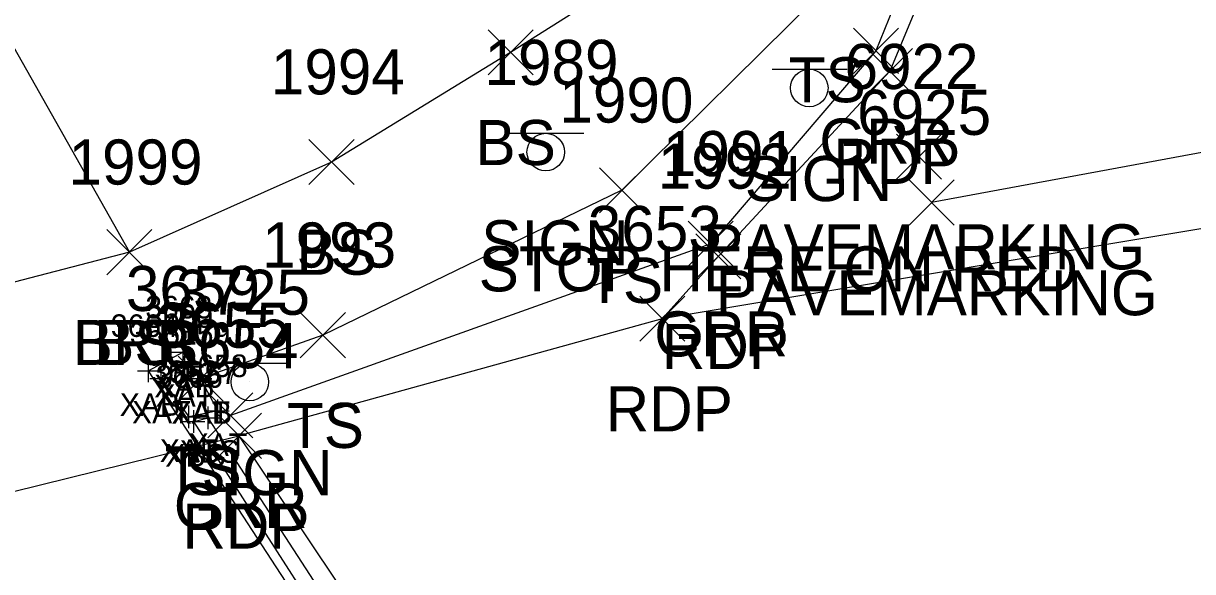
# Model space of a CAD drawing. Extents: x 1505656 to 1508446, y 700805 to 703031.
# Drawn here: x 1506524.5 to 1506576.4, y 701818 to 701842.3 of the extents above; entities that cross this region are included whole.
import ezdxf

# ---------------------------------------------------------------- set-up
doc = ezdxf.new("R2010")
doc.units = 0
for name, color, linetype in [('B_A', 7, 'Continuous'), ('B_I', 7, 'Continuous'), ('B_TIC', 7, 'Continuous'), ('BELB', 7, 'Continuous'), ('BSE', 7, 'Continuous'), ('BSUBM', 7, 'Continuous'), ('L_A', 7, 'Continuous'), ('L_I', 7, 'Continuous'), ('L_TIC', 7, 'Continuous'), ('LABL', 7, 'Continuous'), ('LELB', 7, 'Continuous'), ('P_A', 7, 'Continuous'), ('P_I', 7, 'Continuous'), ('P_TIC', 7, 'Continuous'), ('PET', 7, 'Continuous'), ('R_A', 7, 'Continuous'), ('R_I', 7, 'Continuous'), ('R_TIC', 7, 'Continuous'), ('RGR', 7, 'Continuous'), ('S_A', 7, 'Continuous'), ('S_C', 7, 'Continuous'), ('S_I', 7, 'Continuous'), ('S_TIC', 7, 'Continuous'), ('SSGN', 7, 'Continuous'), ('STS', 7, 'Continuous')]:
    doc.layers.add(name, color=color, linetype=linetype)

msp = doc.modelspace()

# ---------------------------------------------------------------- linework, layer by layer
at = {"layer": 'B_TIC'}
for p, q in [((1506531.566, 701827.682), (1506531.642, 701827.682)), ((1506531.638, 701827.266), (1506531.713, 701827.266)), ((1506530.036, 701826.863), (1506530.112, 701826.863)), ((1506530.036, 701826.863), (1506530.112, 701826.863)), ((1506530.593, 701826.524), (1506530.668, 701826.524)), ((1506532.341, 701826.513), (1506532.417, 701826.513)), ((1506532.341, 701826.513), (1506532.417, 701826.513)), ((1506531.827, 701824.82), (1506531.902, 701824.82)), ((1506531.827, 701824.82), (1506531.902, 701824.82)), ((1506532.035, 701824.61), (1506532.111, 701824.61)), ((1506532.675, 701824.779), (1506532.751, 701824.779)), ((1506532.675, 701824.779), (1506532.751, 701824.779)), ((1506533.107, 701825.083), (1506533.183, 701825.083)), ((1506533.107, 701825.083), (1506533.183, 701825.083))]:
    msp.add_line(p, q, dxfattribs=at)
for points in [[(1506531.563, 701827.182), (1506531.563, 701828.182)], [(1506531.634, 701826.766), (1506531.634, 701827.766)], [(1506530.033, 701826.363), (1506530.033, 701827.363)], [(1506530.033, 701826.363), (1506530.033, 701827.363)], [(1506531.063, 701827.682), (1506532.063, 701827.682)], [(1506531.134, 701827.266), (1506532.134, 701827.266)], [(1506529.533, 701826.863), (1506530.533, 701826.863)], [(1506529.533, 701826.863), (1506530.533, 701826.863)], [(1506530.589, 701826.024), (1506530.589, 701827.024)], [(1506532.338, 701826.013), (1506532.338, 701827.013)], [(1506532.338, 701826.013), (1506532.338, 701827.013)], [(1506530.089, 701826.524), (1506531.089, 701826.524)], [(1506531.838, 701826.513), (1506532.838, 701826.513)], [(1506531.838, 701826.513), (1506532.838, 701826.513)], [(1506531.823, 701824.32), (1506531.823, 701825.32)], [(1506531.823, 701824.32), (1506531.823, 701825.32)], [(1506532.032, 701824.11), (1506532.032, 701825.11)], [(1506532.672, 701824.279), (1506532.672, 701825.279)], [(1506532.672, 701824.279), (1506532.672, 701825.279)], [(1506533.104, 701824.583), (1506533.104, 701825.583)], [(1506533.104, 701824.583), (1506533.104, 701825.583)], [(1506531.323, 701824.82), (1506532.323, 701824.82)], [(1506531.323, 701824.82), (1506532.323, 701824.82)], [(1506531.532, 701824.61), (1506532.532, 701824.61)], [(1506532.172, 701824.779), (1506533.172, 701824.779)], [(1506532.172, 701824.779), (1506533.172, 701824.779)], [(1506532.604, 701825.083), (1506533.604, 701825.083)], [(1506532.604, 701825.083), (1506533.604, 701825.083)]]:
    msp.add_lwpolyline(points, dxfattribs=at)
at = {"layer": 'BELB'}
msp.add_lwpolyline([(1506511.318, 701818.378), (1506534.041, 701823.974)], dxfattribs=at)
at = {"layer": 'BSE'}
for points in [[(1506550.561, 701797.232), (1506549.7, 701797.111), (1506532.032, 701824.61), (1506532.672, 701824.779)], [(1506550.561, 701797.232), (1506532.672, 701824.779)]]:
    msp.add_lwpolyline(points, dxfattribs=at)
at = {"layer": 'BSUBM'}
for points in [[(1506532.338, 701826.513), (1506531.563, 701827.682), (1506530.033, 701826.863)], [(1506533.104, 701825.083), (1506532.338, 701826.513), (1506531.634, 701827.266), (1506530.589, 701826.524), (1506531.823, 701824.82)], [(1506552.506, 701796.25), (1506553.111, 701794.844), (1506551.655, 701793.729), (1506549.57, 701796.872), (1506530.033, 701826.863)], [(1506533.104, 701825.083), (1506531.823, 701824.82)]]:
    msp.add_lwpolyline(points, dxfattribs=at)
at = {"layer": 'L_TIC'}
for points in [[(1506545.101, 701839.985), (1506547.101, 701841.985)], [(1506547.101, 701839.985), (1506545.101, 701841.985)], [(1506537.15, 701835.12), (1506539.15, 701837.12)], [(1506539.15, 701835.12), (1506537.15, 701837.12)], [(1506550.045, 701833.869), (1506552.045, 701835.869)], [(1506552.045, 701833.869), (1506550.045, 701835.869)], [(1506528.177, 701831.12), (1506530.177, 701833.12)], [(1506530.177, 701831.12), (1506528.177, 701833.12)], [(1506528.177, 701831.12), (1506530.177, 701833.12)], [(1506530.177, 701831.12), (1506528.177, 701833.12)], [(1506536.765, 701827.439), (1506538.765, 701829.439)], [(1506538.765, 701827.439), (1506536.765, 701829.439)], [(1506531.338, 701825.513), (1506533.338, 701827.513)], [(1506533.338, 701825.513), (1506531.338, 701827.513)]]:
    msp.add_lwpolyline(points, dxfattribs=at)
at = {"layer": 'LABL'}
msp.add_lwpolyline([(1506097.891, 702451.479), (1506119.326, 702422.589), (1506147.143, 702381.233), (1506170.739, 702339.268), (1506181.047, 702317.334), (1506195.309, 702300.853), (1506204.63, 702289.221), (1506217.936, 702268.002), (1506249.758, 702230.45), (1506275.61, 702192.019), (1506301.13, 702151.48), (1506333.13, 702110.445), (1506362.684, 702074.768), (1506393.244, 702036.244), (1506419.011, 702002.404), (1506440.789, 701985.798), (1506459.199, 701943.611), (1506474.51, 701912.206), (1506491.957, 701880.663), (1506505.674, 701860.234), (1506521.401, 701845.883), (1506529.177, 701832.12), (1506516.383, 701828.815), (1506501.095, 701826.995)], dxfattribs=at)
at = {"layer": 'LELB'}
for points in [[(1506201.907, 702312.635), (1506228.688, 702274.023), (1506255.113, 702234.426), (1506278.209, 702201.234), (1506308.431, 702156.122), (1506338.791, 702114.368), (1506367.336, 702079.99), (1506400.017, 702040.528), (1506426.305, 702009.283), (1506443.257, 701988.04), (1506472.877, 701959.313), (1506500.815, 701931.78), (1506527.025, 701905.238), (1506551.996, 701883.977), (1506559.853, 701877.072), (1506564.801, 701867.875), (1506566.198, 701856.006), (1506560.037, 701843.77), (1506551.045, 701834.869), (1506537.765, 701828.439), (1506532.338, 701826.513)], [(1506469.226, 701954.62), (1506497.214, 701927.752), (1506501.206, 701920.46), (1506510.734, 701914.375), (1506524.681, 701901.803), (1506548.546, 701881.77), (1506555.711, 701872.086), (1506562.612, 701866.355), (1506564.429, 701855.677), (1506556.362, 701847.473), (1506546.101, 701840.985), (1506538.15, 701836.12), (1506529.177, 701832.12)]]:
    msp.add_lwpolyline(points, dxfattribs=at)
at = {"layer": 'P_TIC'}
for points in [[(1506561.935, 701839.149), (1506563.935, 701841.149)], [(1506563.935, 701839.149), (1506561.935, 701841.149)], [(1506554.323, 701830.938), (1506556.323, 701832.938)], [(1506556.323, 701830.938), (1506554.323, 701832.938)], [(1506551.833, 701828.172), (1506553.833, 701830.172)], [(1506553.833, 701828.172), (1506551.833, 701830.172)], [(1506551.833, 701828.172), (1506553.833, 701830.172)], [(1506553.833, 701828.172), (1506551.833, 701830.172)], [(1506533.041, 701822.974), (1506535.041, 701824.974)], [(1506535.041, 701822.974), (1506533.041, 701824.974)]]:
    msp.add_lwpolyline(points, dxfattribs=at)
at = {"layer": 'PET'}
for points in [[(1506503.963, 701935.538), (1506531.718, 701909.612), (1506554.951, 701887), (1506562.539, 701879.069), (1506567.48, 701868.844), (1506568.908, 701854.511), (1506562.935, 701840.149), (1506555.323, 701831.938), (1506552.833, 701829.172), (1506534.041, 701823.974), (1506542.563, 701811.258), (1506550.994, 701798.425), (1506571.308, 701801.753), (1506587.173, 701803.395), (1506614.433, 701806.451), (1506642.201, 701807.517), (1506684.835, 701809.296), (1506720.174, 701808.917), (1506758.847, 701806.498), (1506801.05, 701801.395), (1506837.914, 701794.781)], [(1506681.027, 701845.603), (1506644.047, 701842.709), (1506621.367, 701839.996), (1506603.081, 701837.538), (1506579.919, 701833.682), (1506552.833, 701829.172)]]:
    msp.add_lwpolyline(points, dxfattribs=at)
at = {"layer": 'R_TIC'}
for points in [[(1506561.315, 701840.05), (1506563.315, 701842.05)], [(1506563.315, 701840.05), (1506561.315, 701842.05)], [(1506553.986, 701831.495), (1506555.986, 701833.495)], [(1506555.986, 701831.495), (1506553.986, 701833.495)], [(1506532.66, 701823.882), (1506534.66, 701825.882)], [(1506534.66, 701823.882), (1506532.66, 701825.882)]]:
    msp.add_lwpolyline(points, dxfattribs=at)
at = {"layer": 'RGR'}
msp.add_lwpolyline([(1506194.429, 702325.739), (1506204.07, 702314.524), (1506231.72, 702275.449), (1506257.865, 702236.544), (1506280.914, 702202.923), (1506311.025, 702157.692), (1506341.898, 702115.676), (1506369.199, 702080.673), (1506401.884, 702042.274), (1506429.345, 702011.198), (1506447.039, 701992.434), (1506475.964, 701961.849), (1506503.455, 701934.999), (1506530.822, 701909.192), (1506554.476, 701886.522), (1506561.677, 701878.563), (1506566.908, 701868.507), (1506568.014, 701855.173), (1506562.315, 701841.05), (1506554.986, 701832.495), (1506533.66, 701824.882)], dxfattribs=at)
at = {"layer": 'S_TIC'}
for points in [[(1506563.229, 701835.358), (1506565.229, 701837.358)], [(1506565.229, 701835.358), (1506563.229, 701837.358)], [(1506563.789, 701833.323), (1506565.789, 701835.323)], [(1506565.789, 701833.323), (1506563.789, 701835.323)]]:
    msp.add_lwpolyline(points, dxfattribs=at)
at = {"layer": 'SSGN'}
for p, q in [((1506557.711, 701840.237), (1506561.044, 701840.237)), ((1506559.357, 701839.404), (1506559.357, 701839.404)), ((1506546.012, 701837.394), (1506549.345, 701837.394)), ((1506547.659, 701836.561), (1506547.659, 701836.561)), ((1506532.876, 701827.197), (1506536.21, 701827.197)), ((1506534.523, 701826.364), (1506534.523, 701826.364))]:
    msp.add_line(p, q, dxfattribs=at)
for centre in [(1506559.357, 701839.404), (1506547.659, 701836.561), (1506534.523, 701826.364)]:
    msp.add_circle(centre, 0.833, dxfattribs=at)
at = {"layer": 'STS'}
msp.add_lwpolyline([(1506595.015, 701842.181), (1506595.591, 701840.023), (1506564.789, 701834.323)], dxfattribs=at)

# ---------------------------------------------------------------- texts
at = {"layer": 'B_A'}
for s, p in [('XAB', (1506530.283, 701825.682)), ('XAT', (1506530.339, 701825.266)), ('XAB', (1506528.753, 701824.863)), ('XAB', (1506528.753, 701824.863)), ('XAT', (1506529.294, 701824.524)), ('XAT', (1506531.042, 701824.513)), ('XAB', (1506531.058, 701824.513)), ('XAT', (1506531.808, 701823.083)), ('XAT', (1506531.808, 701823.083)), ('XAT', (1506530.528, 701822.82)), ('XAT', (1506530.528, 701822.82)), ('XBS', (1506530.772, 701822.61)), ('XBS', (1506531.412, 701822.779)), ('XBS', (1506531.412, 701822.779))]:
    msp.add_text(s, height=1, dxfattribs=at).set_placement(p)
at = {"layer": 'B_I'}
for s, p in [('3663', (1506529.886, 701829.182)), ('3660', (1506529.914, 701828.766)), ('3664', (1506528.356, 701828.363)), ('3664', (1506528.356, 701828.363)), ('3661', (1506529.196, 701828.024)), ('3659', (1506530.68, 701828.013)), ('3659', (1506530.68, 701828.013)), ('3662', (1506530.146, 701826.32)), ('3662', (1506530.146, 701826.32)), ('3657', (1506531.018, 701826.279)), ('3657', (1506531.018, 701826.279)), ('3658', (1506531.45, 701826.583)), ('3658', (1506531.45, 701826.583)), ('3656', (1506530.351, 701826.11))]:
    msp.add_text(s, height=1, dxfattribs=at).set_placement(p)
at = {"layer": 'L_A'}
for s, p in [('TS', (1506558.447, 701838.77)), ('BS', (1506544.542, 701835.985)), ('BS', (1506536.59, 701831.12)), ('TS', (1506549.454, 701829.869)), ('BRR', (1506526.665, 701827.12)), ('BS', (1506527.617, 701827.12)), ('TS', (1506536.174, 701823.439)), ('TS', (1506530.747, 701821.513))]:
    msp.add_text(s, height=2, dxfattribs=at).set_placement(p)
at = {"layer": 'L_I'}
for s, p in [('1994', (1506535.457, 701839.12)), ('1990', (1506548.265, 701837.869)), ('1999', (1506526.476, 701835.12)), ('1999', (1506526.476, 701835.12)), ('1993', (1506535.072, 701831.439)), ('3659', (1506529.023, 701829.513))]:
    msp.add_text(s, height=2, dxfattribs=at).set_placement(p)
at = {"layer": 'P_A'}
for p in [(1506560.423, 701835.149), (1506552.811, 701826.938), (1506550.321, 701824.172), (1506550.321, 701824.172), (1506531.529, 701818.974)]:
    msp.add_text('RDP', height=2, dxfattribs=at).set_placement(p)
at = {"layer": 'P_I'}
for s, p in [('1992', (1506552.63, 701834.938)), ('3653', (1506549.526, 701832.172)), ('3653', (1506549.526, 701832.172)), ('3654', (1506530.734, 701826.974))]:
    msp.add_text(s, height=2, dxfattribs=at).set_placement(p)
at = {"layer": 'R_A'}
for p in [(1506559.803, 701836.05), (1506552.474, 701827.495), (1506531.149, 701819.882)]:
    msp.add_text('GRR', height=2, dxfattribs=at).set_placement(p)
at = {"layer": 'R_I'}
for s, p in [('1991', (1506552.86, 701835.495)), ('3655', (1506530.353, 701827.882))]:
    msp.add_text(s, height=2, dxfattribs=at).set_placement(p)
at = {"layer": 'S_A'}
for s, p in [('SIGN', (1506556.495, 701834.384)), ('SIGN', (1506544.797, 701831.54)), ('PAVEMARKING', (1506554.646, 701831.358)), ('PAVEMARKING', (1506555.207, 701829.323)), ('SIGN', (1506531.661, 701821.344))]:
    msp.add_text(s, height=2, dxfattribs=at).set_placement(p)
at = {"layer": 'S_C'}
msp.add_text('STOP HERE ON RED', height=2, dxfattribs=at).set_placement((1506544.684, 701830.384))
at = {"layer": 'S_I'}
for s, p in [('1989', (1506544.939, 701839.54)), ('6922', (1506560.922, 701839.358)), ('6925', (1506561.482, 701837.323)), ('3725', (1506531.244, 701829.344))]:
    msp.add_text(s, height=2, dxfattribs=at).set_placement(p)

doc.saveas('drawing.dxf')
